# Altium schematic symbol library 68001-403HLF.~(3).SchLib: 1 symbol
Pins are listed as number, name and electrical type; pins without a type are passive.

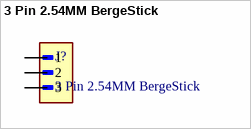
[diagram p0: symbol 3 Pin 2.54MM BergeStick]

## 3 Pin 2.54MM BergeStick
designator J?
3 Pin 3Pos THT BergeStick 2.54MM Amphenol 68001-403HLF 3A
footprint AMPHENOL_68001-403HLF
pins: 1, 2, 3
